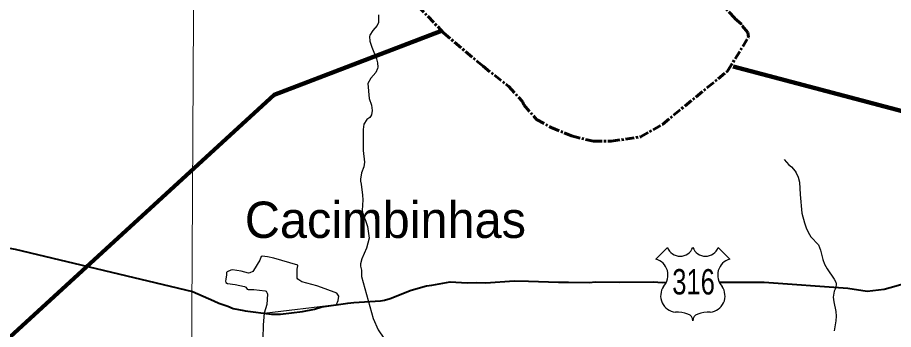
# Model space of a CAD drawing. Extents: x 553962 to 842807, y 8883888 to 9032388.
# Drawn here: x 717226 to 729266, y 8959632 to 8963926 of the extents above; entities that cross this region are included whole.
import ezdxf
from ezdxf.enums import TextEntityAlignment as Align

# ---------------------------------------------------------------- set-up
doc = ezdxf.new("R2010")
doc.units = 0
doc.header["$LTSCALE"] = 20
doc.linetypes.add('LONG_DASH_SHORT_DASH', pattern=[9.9, 6, -1.2, 1.5, -1.2])
for name, color, linetype, lineweight in [('1', 7, 'Continuous', 13), ('12', 7, 'Continuous', 25), ('21', 7, 'Continuous', 25), ('24', 7, 'Continuous', 25), ('48', 7, 'Continuous', 25), ('7', 7, 'LONG_DASH_SHORT_DASH', 60), ('9', 7, 'Continuous', 90)]:
    doc.layers.add(name, color=color, linetype=linetype, lineweight=lineweight)
doc.layers.add('41', color=7, linetype='Continuous')

msp = doc.modelspace()

# ---------------------------------------------------------------- linework, layer by layer
at = {"layer": '1'}
msp.add_lwpolyline([(719978.92, 9023574.47), (719561.64, 8949232.17), (719215.63, 8890710.6)], dxfattribs=at)
at = {"layer": '12', "lineweight": 40}
for points in [[(710551.51, 8961397.11), (711177.13, 8961501.21), (712015.98, 8961727.13), (712358.95, 8961724.17), (713550.71, 8961508.18), (716056.52, 8960938.01), (717193.53, 8960736.2), (719630.35, 8960157.34)], [(727488.2, 8960282.3), (728636.39, 8960199.63), (728903.43, 8960161.82), (729137.06, 8960189.26), (729219.73, 8960208.11), (729400.96, 8960258.8), (729465.41, 8960280.38), (729590.56, 8960330.01), (729719.37, 8960362.95), (729852.47, 8960406.02), (729968.99, 8960418.16), (730064.27, 8960434.81), (730362.78, 8960475.91), (730505.92, 8960510.9), (731000.54, 8960614.44), (731116.07, 8960622.55), (731172.08, 8960636.38), (731339.7, 8960662.29), (731644.16, 8960700.61)], [(721922.86, 8960008.98), (722213.68, 8960025.38), (722269.75, 8960036.41), (722349.07, 8960058.36), (722636.07, 8960173.14), (722845.74, 8960234.4), (722922.45, 8960243.46), (723174, 8960287.25), (723408.07, 8960273.78), (723541.67, 8960277.89), (723662.4, 8960276.13), (724053.37, 8960301.27), (724251.47, 8960299.1), (724661.82, 8960282.63), (724797.4, 8960284.36), (725081.13, 8960280.45), (725171.78, 8960288.14), (725504.31, 8960282.44), (725962.14, 8960286.19), (726091.1, 8960280.31), (726144.94, 8960281.86)], [(726871.36, 8960282.36), (727184.23, 8960282.33), (727488.2, 8960282.3)], [(719630.35, 8960157.34), (719924.91, 8960025.02), (719991.14, 8959995.23), (720116.07, 8959954.92), (720192.17, 8959919.6), (720337.51, 8959893.81), (720356.6, 8959891.3)], [(721309.89, 8959913.93), (721410.94, 8959945.92), (721766.76, 8959996.78), (721847.46, 8960004.73), (721922.86, 8960008.98)], [(720356.6, 8959891.3), (720717.07, 8959843.9), (720842.5, 8959844.23), (721142.71, 8959881.74), (721309.89, 8959913.93)]]:
    msp.add_lwpolyline(points, dxfattribs=at)
at = {"layer": '12'}
msp.add_lwpolyline([(720615.19, 8959855.53), (720600.92, 8959695.18), (720597, 8959505.12), (720630.53, 8959292.24), (720652.78, 8959055.03), (720632.13, 8958659.52), (720634.96, 8958462.04), (720656.08, 8958337.22), (720700.75, 8958191.79), (720743.23, 8958010.86), (720791.05, 8957885.8), (720852.55, 8957752.88), (720877.22, 8957688.21), (720887.96, 8957623.77), (720908.94, 8957434.41), (720919.79, 8957236.89), (720915.83, 8956822.81), (720917.49, 8956475.5), (720890.25, 8956243.67), (720885.83, 8956166.34), (720886.76, 8956088.94), (720868.93, 8955947.06), (720826.49, 8955484.84)], dxfattribs=at)
at = {"layer": '21'}
for points in [[(721081.19, 8960508.09), (721077.36, 8960519.08), (720747.73, 8960615.24), (720662.87, 8960634.12), (720587.23, 8960643.04), (720575.8, 8960636.94), (720555.95, 8960586.94), (720470.64, 8960443.56), (720458.93, 8960429.95), (720418.07, 8960410.71), (720402.2, 8960408.32), (720301.94, 8960437.17), (720180.96, 8960453.16), (720156.06, 8960451.22), (720109.05, 8960428.1), (720098.94, 8960418.47), (720097.94, 8960382.44), (720087.73, 8960324.77), (720086.65, 8960296.8), (720091.32, 8960280.84), (720111.5, 8960263.57), (720216.22, 8960251.9), (720344.15, 8960222.51), (720362.43, 8960213.99), (720382.84, 8960187.98), (720394.39, 8960180.67), (720474.69, 8960182.32), (720628.88, 8960163.31), (720641.89, 8960157.8), (720658.42, 8960133.88), (720662.78, 8960119.51), (720650.84, 8959977.92), (720618.37, 8959856.94), (721612.37, 8959974.73)], [(721612.37, 8959974.73), (721632.45, 8960032.67), (721644.09, 8960093.19), (721613.99, 8960131.42), (721452.88, 8960193.91), (721340.22, 8960231.68), (721132.49, 8960290.65), (721077.96, 8960323.44), (721071.99, 8960337.7), (721069.21, 8960462.3), (721081.19, 8960508.09)]]:
    msp.add_lwpolyline(points, dxfattribs=at)
at = {"layer": '24'}
for points in [[(722187.02, 8963962.13), (722189.12, 8963859.11), (722167.65, 8963817.47), (722110.52, 8963747.66), (722070.31, 8963681.69), (722063.85, 8963664.37), (722068.13, 8963601.07), (722094.02, 8963516.08), (722162.58, 8963358.05), (722176.19, 8963303.12), (722177.02, 8963243.97), (722173.57, 8963222.99), (722150.39, 8963167.13), (722082.19, 8963092.31), (722039.21, 8963017.96), (722060.45, 8962810.22), (722090.51, 8962720.73), (722103.06, 8962648.54), (722089.59, 8962588.76), (722078.75, 8962562.78), (722066.78, 8962550.56), (722025.2, 8962521.79), (721986.8, 8962458.04), (721977.95, 8962384.96), (721975.35, 8962231.74), (721979.04, 8962096.03), (721995.31, 8961934.23), (721985.76, 8961870.18), (721954.42, 8961789.14)], [(727765.81, 8961970.33), (727825.76, 8961899), (727865.14, 8961870.76), (727914.39, 8961812.86), (727928.86, 8961790.78), (727956.99, 8961730.57), (727973.65, 8961658.34), (727982.14, 8961491.7), (728008.27, 8961232.55), (728042.47, 8961100.94), (728042.47, 8961100.94)], [(721954.42, 8961789.14), (721939.02, 8961701.54), (721940.48, 8961675.57), (721951.86, 8961632), (721968.94, 8961483.45), (721970.49, 8961415.5), (721961.26, 8961270.98), (721974.83, 8961199.11), (722002.53, 8961147.87), (722036.12, 8961049.74), (722059.04, 8960887.06), (722022.21, 8960752.44), (721958.84, 8960603.27), (721941.35, 8960535.41), (721939.85, 8960504.44), (721951.95, 8960451.18), (721953.64, 8960363.86)], [(728042.47, 8961100.94), (728066.84, 8961029.37), (728091.55, 8960973.47), (728132.07, 8960907.81), (728236.64, 8960797.53), (728265.06, 8960722.42), (728295.65, 8960595.04), (728318.98, 8960531.31), (728352.93, 8960467.55), (728449.56, 8960324.91), (728474.61, 8960281.82), (728477.38, 8960259.13), (728473.93, 8960207.96), (728448.65, 8960158.96), (728438.42, 8960076.08), (728447.62, 8960012.28), (728475.26, 8959880.63), (728477.72, 8959816.9), (728475.26, 8959753.17), (728452.11, 8959613.38)], [(721953.64, 8960363.86), (722093.57, 8959865.13), (722115.37, 8959783.03), (722181.94, 8959629.94), (722261.14, 8959510.91)]]:
    msp.add_lwpolyline(points, dxfattribs=at)
at = {"layer": '48'}
for p, q in [((725998.68, 8960601.99), (726158.61, 8960761.89)), ((726857.93, 8960761.89), (727017.88, 8960601.99))]:
    msp.add_line(p, q, dxfattribs=at)
for centre, radius, start, end in [((726333.44, 8960828.86), 187.21, 200.95927, 339.04073), ((726683.09, 8960828.86), 187.21, 200.95927, 339.04073), ((725936.61, 8960380.12), 230.34, 317.5721, 74.36886), ((727079.93, 8960380.12), 230.34, 105.62774, 222.4279), ((726290.1, 8960094.98), 224.71, 144.73733, 264.65778), ((726726.43, 8960094.98), 224.71, 275.34222, 35.26267), ((726268.16, 8959281.51), 589.74, 72.89371, 89.90057), ((726748.38, 8959281.51), 589.74, 90.09943, 107.10629), ((726413.91, 8959754.88), 94.44, 357.69345, 72.92955), ((726602.63, 8959754.88), 94.44, 107.07045, 182.30655)]:
    msp.add_arc(centre, radius, start, end, dxfattribs=at)
at = {"layer": '7'}
msp.add_lwpolyline([(722178.5, 8964656.96), (723083.39, 8963715.25), (723625.78, 8963254.3), (723977.78, 8962977.11), (724168.21, 8962768.69), (724186.85, 8962722.91), (724359.5, 8962523.16), (724559.39, 8962414.17), (724841.09, 8962296.13), (725140.97, 8962223.5), (725386.83, 8962222.51), (725788.64, 8962283.2), (726090.28, 8962454.16), (726984.44, 8963189.69), (727272.89, 8963654.04), (727265.07, 8963720.49), (727171.43, 8963825.9), (727177.24, 8963835.72), (727083.5, 8963916.64), (726881.43, 8964145.75)], dxfattribs=at)
at = {"layer": '9'}
msp.add_line((738230.17, 8960292.86), (727062.75, 8963254.11), dxfattribs=at)
msp.add_lwpolyline([(705081.22, 8958366.77), (705509.17, 8948874.18), (720755.9, 8962863.64), (723053.57, 8963740.6)], dxfattribs=at)

# ---------------------------------------------------------------- texts
at = {"layer": '41'}
msp.add_text('Cacimbinhas', height=500, dxfattribs=at).set_placement((720350.27, 8960892.53))
at = {"layer": '48', "width": 0.75}
msp.add_text('316', height=350, dxfattribs=at).set_placement((726518.2, 8960114.2), align=Align.CENTER)

doc.saveas('drawing.dxf')
